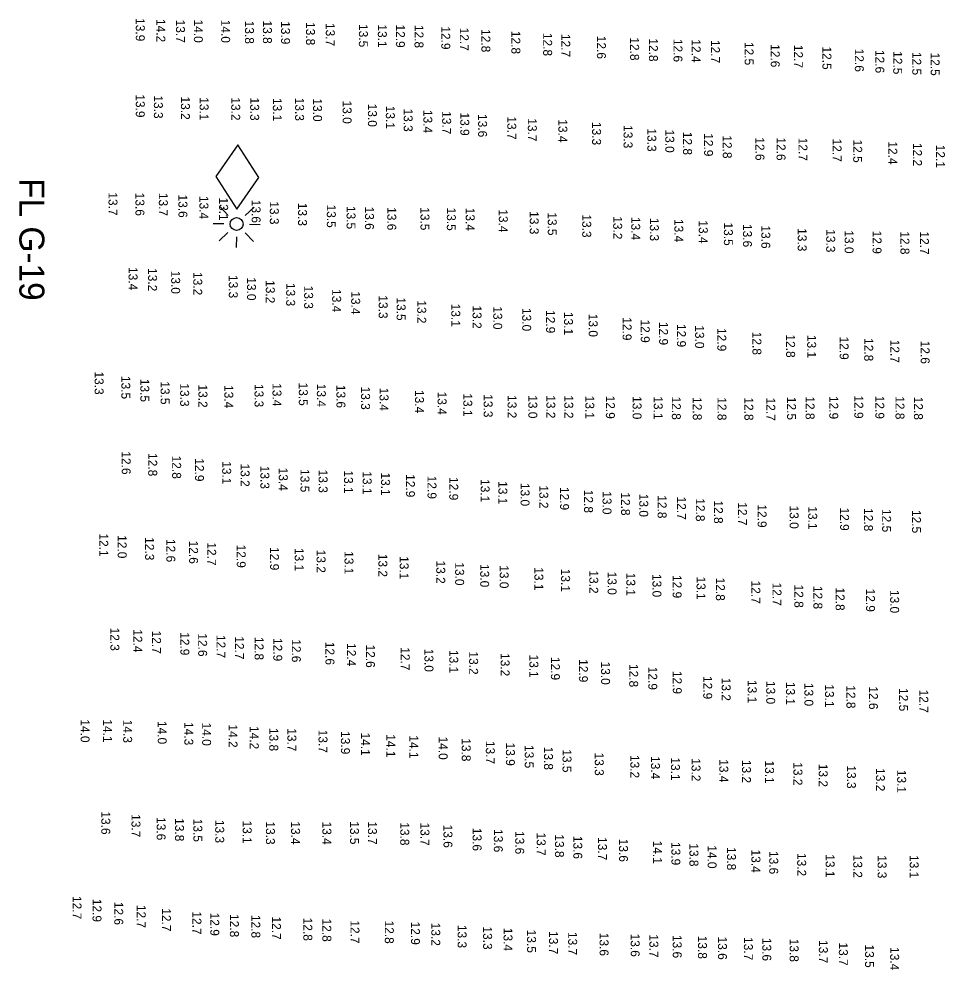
# Model space of a CAD drawing. Extents: x 988130 to 1132882, y 654656 to 841453.
# Drawn here: x 1109665 to 1110184, y 669094 to 669627 of the extents above; entities that cross this region are included whole.
import ezdxf

# ---------------------------------------------------------------- set-up
doc = ezdxf.new("R2010")
doc.units = 0
doc.layers.add('V-CHAN-NAID', color=7, linetype='Continuous')
doc.layers.add('V-TOPO-SOUN', color=7, linetype='Continuous')

msp = doc.modelspace()

# ---------------------------------------------------------------- linework, layer by layer
at = {"layer": 'V-CHAN-NAID'}
for p, q in [((1109781.78, 669517.3), (1109777.07, 669522.19)), ((1109791.38, 669517.14), (1109796.27, 669521.85)), ((1109779.3, 669512.55), (1109773.3, 669512.65)), ((1109793.7, 669512.29), (1109799.7, 669512.19)), ((1109776.73, 669502.99), (1109781.62, 669507.7)), ((1109795.93, 669502.65), (1109791.22, 669507.54)), ((1109786.37, 669505.22), (1109786.27, 669499.22))]:
    msp.add_line(p, q, dxfattribs=at)
msp.add_lwpolyline([(1109786.65, 669520.82), (1109798.96, 669538.61), (1109787.27, 669556.81), (1109774.96, 669539.03)], close=True, dxfattribs=at)
msp.add_circle((1109786.5, 669512.42), 3.6, dxfattribs=at)

# ---------------------------------------------------------------- texts
msp.add_text('FL G-19', height=14, rotation=270, dxfattribs=at).set_placement((1109664.76, 669538.17))
at = {"layer": 'V-TOPO-SOUN'}
for s, p in [('13.9 ', (1109730.03, 669627.83)), ('14.2 ', (1109741.59, 669627.32)), ('13.7 ', (1109752.54, 669626.98)), ('14.0 ', (1109762.56, 669627.03)), ('14.0 ', (1109777.87, 669626.93)), ('13.8 ', (1109791.22, 669626.38)), ('13.8 ', (1109801.28, 669626.49)), ('13.9 ', (1109811.45, 669626.12)), ('13.8 ', (1109825.44, 669625.61)), ('13.7 ', (1109836.52, 669625.1)), ('13.5 ', (1109855.06, 669624.5)), ('13.1 ', (1109865.69, 669624.29)), ('12.9 ', (1109875.82, 669624.25)), ('12.8 ', (1109886.24, 669624.05)), ('12.9 ', (1109901.24, 669623.23)), ('12.7 ', (1109911.63, 669622.48)), ('12.8 ', (1109923.73, 669621.67)), ('12.8 ', (1109940.54, 669620.7)), ('12.8 ', (1109958.34, 669619.57)), ('12.7 ', (1109968.51, 669618.99)), ('12.6 ', (1109988.47, 669617.94)), ('12.8 ', (1110007.09, 669617.06)), ('12.8 ', (1110017.62, 669616.49)), ('12.6 ', (1110031.38, 669616.19)), ('12.4 ', (1110041.58, 669615.93)), ('12.7 ', (1110052.36, 669615.59)), ('12.5 ', (1110071.25, 669614.45)), ('12.6 ', (1110085.91, 669613.24)), ('12.7 ', (1110098.86, 669612.87)), ('12.5 ', (1110114.87, 669611.94)), ('12.6 ', (1110133.01, 669610.71)), ('12.6 ', (1110144.53, 669609.99)), ('12.5 ', (1110154.53, 669609.31)), ('12.5 ', (1110165.2, 669608.88)), ('12.5 ', (1110175.53, 669608.53)), ('13.9 ', (1109730.03, 669585.14)), ('13.3 ', (1109740.16, 669584.53)), ('13.2 ', (1109755.32, 669583.91)), ('13.1 ', (1109765.79, 669583.52)), ('13.2 ', (1109783.51, 669583.44)), ('13.3 ', (1109794.14, 669583.36)), ('13.1 ', (1109806.84, 669583.06)), ('13.3 ', (1109819.32, 669583.23)), ('13.0 ', (1109829.38, 669582.84)), ('13.0 ', (1109845.96, 669581.63)), ('13.0 ', (1109860.12, 669579.88)), ('13.1 ', (1109870.17, 669578.73)), ('13.3 ', (1109880.18, 669577.17)), ('13.4 ', (1109891.2, 669576.41)), ('13.7 ', (1109901.74, 669575.69)), ('13.9 ', (1109911.9, 669574.94)), ('13.6 ', (1109921.88, 669574.09)), ('13.7 ', (1109938.23, 669572.77)), ('13.7 ', (1109949.74, 669571.72)), ('13.4 ', (1109966.88, 669571.13)), ('13.3 ', (1109985.78, 669569.66)), ('13.3 ', (1110003.4, 669567.88)), ('13.3 ', (1110016.74, 669566.02)), ('13.0 ', (1110026.78, 669565.4)), ('12.8 ', (1110036.74, 669564.12)), ('12.9 ', (1110048.51, 669563.34)), ('12.8 ', (1110059.02, 669562.16)), ('12.6 ', (1110077.32, 669561.04)), ('12.6 ', (1110089.16, 669561.01)), ('12.7 ', (1110101.44, 669560.82)), ('12.7 ', (1110120.55, 669560.32)), ('12.5 ', (1110132.1, 669559.8)), ('12.4 ', (1110151.78, 669558.76)), ('12.2 ', (1110165.6, 669557.89)), ('12.1 ', (1110178.46, 669556.89)), ('13.7 ', (1109714.73, 669530.2)), ('13.6 ', (1109729.83, 669530.01)), ('13.7 ', (1109742.93, 669529.91)), ('13.6 ', (1109753.93, 669529)), ('13.4 ', (1109765.7, 669528.21)), ('13.1 ', (1109776.73, 669527.34)), ('13.6 ', (1109794.94, 669526.06)), ('13.3 ', (1109805.14, 669525.2)), ('13.3 ', (1109820.97, 669524.35)), ('13.5 ', (1109837.1, 669523.37)), ('13.5 ', (1109848.14, 669522.59)), ('13.6 ', (1109858.49, 669522.24)), ('13.6 ', (1109870.97, 669521.9)), ('13.5 ', (1109889.58, 669521.89)), ('13.5 ', (1109904.36, 669521.68)), ('13.4 ', (1109914.94, 669521.58)), ('13.4 ', (1109933.48, 669520.72)), ('13.3 ', (1109950.81, 669519.66)), ('13.5 ', (1109960.93, 669519.03)), ('13.3 ', (1109980.24, 669517.85)), ('13.2 ', (1109997.59, 669516.84)), ('13.4 ', (1110007.7, 669516.45)), ('13.3 ', (1110018.15, 669515.91)), ('13.4 ', (1110031.87, 669515.28)), ('13.4 ', (1110045.57, 669514.51)), ('13.5 ', (1110059.63, 669513.31)), ('13.6 ', (1110070.32, 669512.48)), ('13.6 ', (1110080.6, 669511.69)), ('13.3 ', (1110101.01, 669510.14)), ('13.3 ', (1110116.97, 669509.55)), ('13.0 ', (1110127.3, 669508.92)), ('12.9 ', (1110142.95, 669508.73)), ('12.8 ', (1110158.59, 669508.38)), ('12.7 ', (1110169.56, 669508.3)), ('13.4 ', (1109725.98, 669488.35)), ('13.2 ', (1109736.93, 669487.75)), ('13.0 ', (1109749.85, 669486.3)), ('13.2 ', (1109762.23, 669485.54)), ('13.3 ', (1109782.15, 669483.9)), ('13.0 ', (1109792.37, 669482.62)), ('13.2 ', (1109802.89, 669481.01)), ('13.3 ', (1109814.31, 669479.43)), ('13.3 ', (1109824.39, 669477.92)), ('13.4 ', (1109840.09, 669475.99)), ('13.4 ', (1109850.75, 669474.75)), ('13.3 ', (1109866.16, 669472.49)), ('13.5 ', (1109876.21, 669471.32)), ('13.2 ', (1109887.76, 669469.73)), ('13.1 ', (1109906.84, 669467.83)), ('13.2 ', (1109918.77, 669466.8)), ('13.0 ', (1109930.35, 669466.36)), ('13.0 ', (1109946.59, 669465.41)), ('12.9 ', (1109959.98, 669464.23)), ('13.1 ', (1109970.03, 669463.22)), ('13.0 ', (1109983.86, 669462.17)), ('12.9 ', (1110002.87, 669460.22)), ('12.9 ', (1110013.05, 669458.93)), ('12.9 ', (1110023.3, 669457.6)), ('12.9 ', (1110033.32, 669456.47)), ('13.0 ', (1110043.52, 669455.74)), ('12.9 ', (1110055.95, 669454.18)), ('12.8 ', (1110075.64, 669452.1)), ('12.8 ', (1110094.51, 669450.58)), ('13.1 ', (1110106.31, 669450.34)), ('12.9 ', (1110124.49, 669449.42)), ('12.8 ', (1110138.29, 669448.54)), ('12.7 ', (1110152.98, 669447.64)), ('12.6 ', (1110169.93, 669447.08)), ('13.3 ', (1109706.96, 669429.84)), ('13.5 ', (1109721.93, 669427.35)), ('13.5 ', (1109732.56, 669425.73)), ('13.5 ', (1109743.93, 669424.33)), ('13.3 ', (1109754.9, 669423.18)), ('13.2 ', (1109765.15, 669422.56)), ('13.4 ', (1109779.65, 669422.22)), ('13.3 ', (1109796.58, 669422.83)), ('13.4 ', (1109806.64, 669423.28)), ('13.5 ', (1109821.39, 669423.63)), ('13.4 ', (1109831.51, 669422.94)), ('13.6 ', (1109842.49, 669422.35)), ('13.3 ', (1109856.3, 669421.39)), ('13.4 ', (1109866.64, 669420.73)), ('13.4 ', (1109886.5, 669419.46)), ('13.4 ', (1109899.17, 669418.55)), ('13.1 ', (1109913.57, 669417.58)), ('13.3 ', (1109924.98, 669417.08)), ('13.2 ', (1109938.39, 669416.59)), ('13.0 ', (1109950.04, 669416.53)), ('13.2 ', (1109960.13, 669416.54)), ('13.2 ', (1109970.19, 669416.49)), ('13.1 ', (1109981.96, 669416.27)), ('12.9 ', (1109993.49, 669416.31)), ('13.0 ', (1110008.45, 669416.02)), ('13.1 ', (1110020.31, 669415.94)), ('12.8 ', (1110030.46, 669415.76)), ('12.5 ', (1110095.05, 669415.63)), ('12.8 ', (1110105.42, 669415.89)), ('12.9 ', (1110118.68, 669416.12)), ('12.9 ', (1110132.71, 669416.43)), ('12.9 ', (1110144.51, 669416.25)), ('12.8 ', (1110155.8, 669415.96)), ('12.8 ', (1110166.13, 669415.69)), ('12.8 ', (1110042.21, 669415.47)), ('12.8 ', (1110056.04, 669415.41)), ('12.8 ', (1110071.12, 669415.32)), ('12.7 ', (1110083.39, 669415.22)), ('12.6 ', (1109722.14, 669385.09)), ('12.8 ', (1109737, 669384.11)), ('12.8 ', (1109750.41, 669382.68)), ('12.9 ', (1109763.2, 669381.21)), ('13.1 ', (1109778.45, 669379.57)), ('13.2 ', (1109788.77, 669378.25)), ('13.3 ', (1109799.88, 669377.02)), ('13.4 ', (1109810.17, 669375.95)), ('13.5 ', (1109822.33, 669375.13)), ('13.3 ', (1109832.48, 669374.85)), ('13.1 ', (1109846.74, 669374.42)), ('13.1 ', (1109857.21, 669373.89)), ('13.1 ', (1109867.52, 669373.25)), ('12.9 ', (1109881.42, 669372.32)), ('12.9 ', (1109893.52, 669371.43)), ('12.9 ', (1109905.69, 669370.68)), ('13.1 ', (1109923.29, 669369.53)), ('13.1 ', (1109933.24, 669368.37)), ('13.0 ', (1109945.68, 669367.39)), ('13.2 ', (1109956.16, 669366.06)), ('12.9 ', (1109967.8, 669365.13)), ('12.8 ', (1109981.27, 669363.55)), ('13.0 ', (1109991.61, 669362.73)), ('12.8 ', (1110002.02, 669362.11)), ('13.0 ', (1110012.2, 669361.31)), ('12.8 ', (1110022.49, 669360.49)), ('12.7 ', (1110033.38, 669359.74)), ('12.8 ', (1110043.9, 669358.78)), ('12.8 ', (1110054.05, 669357.57)), ('12.7 ', (1110067.58, 669356.54)), ('12.9 ', (1110078.56, 669355.36)), ('13.0 ', (1110096.49, 669354.7)), ('13.1 ', (1110106.89, 669354.27)), ('12.9 ', (1110124.76, 669353.61)), ('12.8 ', (1110138.15, 669353.28)), ('12.5 ', (1110148.33, 669352.76)), ('12.5 ', (1110165.05, 669352.23)), ('12.1 ', (1109709.57, 669339.08)), ('12.0 ', (1109719.89, 669338.12)), ('12.3 ', (1109735.26, 669337)), ('12.6 ', (1109747.16, 669335.98)), ('12.6 ', (1109759.9, 669335.06)), ('12.7 ', (1109770.05, 669334.08)), ('12.9 ', (1109786.61, 669332.81)), ('12.9 ', (1109805.29, 669331.42)), ('13.1 ', (1109819.1, 669330.96)), ('13.2 ', (1109831.35, 669329.98)), ('13.1 ', (1109847, 669329.15)), ('13.2 ', (1109866, 669327.68)), ('13.1 ', (1109877.94, 669326.35)), ('13.2 ', (1109898.42, 669323.91)), ('13.0 ', (1109909.02, 669322.91)), ('13.0 ', (1109923.05, 669321.92)), ('13.0 ', (1109933.97, 669321.28)), ('13.1 ', (1109953.43, 669320.15)), ('13.1 ', (1109968.41, 669319.31)), ('13.2 ', (1109984.18, 669318.38)), ('13.0 ', (1109994.45, 669317.69)), ('13.1 ', (1110004.98, 669317.06)), ('13.0 ', (1110019.59, 669316.37)), ('12.9 ', (1110030.91, 669315.8)), ('13.1 ', (1110044.3, 669314.94)), ('12.8 ', (1110055.14, 669314.33)), ('12.7 ', (1110075.04, 669312.68)), ('12.7 ', (1110086.88, 669311.52)), ('12.8 ', (1110099.15, 669310.44)), ('12.8 ', (1110109.81, 669309.69)), ('12.8 ', (1110122.25, 669308.81)), ('12.9 ', (1110139.3, 669308.14)), ('13.0 ', (1110152.82, 669307.41)), ('12.3 ', (1109715.79, 669286.3)), ('12.4 ', (1109728.59, 669285.4)), ('12.7 ', (1109739.15, 669284.64)), ('12.9 ', (1109755, 669283.76)), ('12.6 ', (1109764.98, 669283.11)), ('12.7 ', (1109775.26, 669282.22)), ('12.7 ', (1109785.64, 669281.45)), ('12.8 ', (1109796.62, 669281.12)), ('12.9 ', (1109807.06, 669280.49)), ('12.6 ', (1109817.48, 669279.83)), ('12.6 ', (1109836.33, 669278.37)), ('12.4 ', (1109848.38, 669277.64)), ('12.6 ', (1109859.03, 669276.85)), ('12.7 ', (1109878.55, 669275.31)), ('13.0 ', (1109891.82, 669274.5)), ('13.1 ', (1109905.72, 669273.78)), ('13.2 ', (1109916.86, 669272.97)), ('13.2 ', (1109934.51, 669272.04)), ('13.1 ', (1109950.64, 669271.24)), ('12.9 ', (1109962.67, 669269.9)), ('12.9 ', (1109978.37, 669268.66)), ('13.0 ', (1109990.8, 669267.3)), ('12.8 ', (1110006.55, 669265.95)), ('12.9 ', (1110017.26, 669264.42)), ('12.9 ', (1110031, 669262.09)), ('12.9 ', (1110048.04, 669259.2)), ('13.2 ', (1110058.4, 669258.24)), ('13.1 ', (1110073.02, 669256.96)), ('13.0 ', (1110083.34, 669256.45)), ('13.1 ', (1110094.46, 669255.92)), ('13.0 ', (1110104.75, 669255.34)), ('13.1 ', (1110116.29, 669254.57)), ('12.8 ', (1110128.31, 669253.99)), ('12.6 ', (1110140.91, 669253.43)), ('12.5 ', (1110157.84, 669252.45)), ('12.7 ', (1110169.19, 669251.57)), ('14.0 ', (1109699.12, 669234.92)), ('14.1 ', (1109711.72, 669234.94)), ('14.3 ', (1109722.95, 669234.71)), ('14.0 ', (1109742.31, 669234)), ('14.3 ', (1109757.22, 669233.41)), ('14.0 ', (1109767.22, 669233.1)), ('14.2 ', (1109782.01, 669232.06)), ('14.2 ', (1109793.92, 669231.17)), ('13.8 ', (1109804.84, 669230.11)), ('13.7 ', (1109815, 669229.95)), ('13.7 ', (1109832.43, 669229.12)), ('13.9 ', (1109844.99, 669228.33)), ('14.1 ', (1109856.21, 669227.53)), ('14.1 ', (1109870.46, 669226.59)), ('14.1 ', (1109883.38, 669225.97)), ('14.0 ', (1109899.8, 669225.3)), ('13.8 ', (1109912.71, 669224.34)), ('13.7 ', (1109926.21, 669222.85)), ('13.9 ', (1109937.46, 669221.89)), ('13.5 ', (1109948.03, 669220.54)), ('13.8 ', (1109958.82, 669219.56)), ('13.5 ', (1109969.19, 669218.15)), ('13.3 ', (1109987.28, 669216.32)), ('13.2 ', (1110007.21, 669214.97)), ('13.4 ', (1110018.76, 669214.33)), ('13.1 ', (1110029.97, 669213.61)), ('13.2 ', (1110041.5, 669213.15)), ('13.4 ', (1110057.06, 669212.58)), ('13.2 ', (1110069.78, 669212.21)), ('13.1 ', (1110082.73, 669211.87)), ('13.2 ', (1110098.62, 669210.88)), ('13.2 ', (1110112.8, 669210.01)), ('13.3 ', (1110128.58, 669209.12)), ('13.2 ', (1110144.83, 669207.59)), ('13.1 ', (1110156.75, 669206.63)), ('13.6 ', (1109710.69, 669183.36)), ('13.7 ', (1109727.61, 669181.81)), ('13.6 ', (1109741.72, 669180.15)), ('13.8 ', (1109752.03, 669179.56)), ('13.5 ', (1109762.3, 669179.24)), ('13.3 ', (1109774.54, 669178.6)), ('13.1 ', (1109789.97, 669178.23)), ('13.3 ', (1109802.96, 669177.73)), ('13.4 ', (1109817.07, 669177.78)), ('13.4 ', (1109834.62, 669177.66)), ('13.5 ', (1109850.1, 669177.82)), ('13.7 ', (1109860.13, 669177.75)), ('13.8 ', (1109878.25, 669177.24)), ('13.7 ', (1109889.57, 669177.11)), ('13.6 ', (1109902.46, 669175.93)), ('13.6 ', (1109918.79, 669174.14)), ('13.6 ', (1109930.7, 669173.42)), ('13.6 ', (1109942.69, 669172.33)), ('13.7 ', (1109954.74, 669171.51)), ('13.8 ', (1109964.98, 669170.48)), ('13.6 ', (1109975.25, 669169.66)), ('13.7 ', (1109989.08, 669168.93)), ('13.6 ', (1110000.86, 669168.03)), ('14.1 ', (1110019.95, 669166.94)), ('13.9 ', (1110030.22, 669166.18)), ('13.8 ', (1110040.33, 669165.46)), ('14.0 ', (1110050.53, 669164.36)), ('13.8 ', (1110061.36, 669163.36)), ('13.4 ', (1110075.08, 669161.99)), ('13.6 ', (1110085.05, 669161.14)), ('13.2 ', (1110100.71, 669160.01)), ('13.1 ', (1110116.66, 669159.33)), ('13.2 ', (1110132.12, 669159.08)), ('13.3 ', (1110145.78, 669158.81)), ('13.1 ', (1110163.75, 669158.89)), ('12.7 ', (1109694.57, 669135.94)), ('12.9 ', (1109705.78, 669134.37)), ('12.6 ', (1109717.94, 669132.67)), ('12.7 ', (1109730.59, 669130.98)), ('12.7 ', (1109744.66, 669129.08)), ('12.7 ', (1109761.78, 669127.32)), ('12.9 ', (1109771.77, 669126.61)), ('12.8 ', (1109782.76, 669125.82)), ('12.8 ', (1109794.78, 669125.36)), ('12.7 ', (1109806.38, 669124.45)), ('12.8 ', (1109823.93, 669123.79)), ('12.8 ', (1109834.6, 669123.3)), ('12.7 ', (1109850.36, 669122.28)), ('12.8 ', (1109869.6, 669122.18)), ('12.9 ', (1109884.26, 669121.58)), ('13.2 ', (1109895.63, 669120.98)), ('13.3 ', (1109910.39, 669119.76)), ('13.3 ', (1109924.69, 669118.9)), ('13.4 ', (1109936.13, 669118.11)), ('13.5 ', (1109949.32, 669117.06)), ('13.7 ', (1109961.63, 669116.26)), ('13.7 ', (1109972.35, 669115.79)), ('13.6 ', (1109989.96, 669115.33)), ('13.6 ', (1110007.42, 669114.85)), ('13.7 ', (1110017.89, 669114.45)), ('13.6 ', (1110030.96, 669114.11)), ('13.8 ', (1110045.11, 669113.69)), ('13.6 ', (1110056.32, 669113.21)), ('13.7 ', (1110070.84, 669112.92)), ('13.6 ', (1110081.18, 669112.48)), ('13.8 ', (1110096.5, 669112)), ('13.7 ', (1110112.85, 669111.23)), ('13.7 ', (1110124.07, 669109.88)), ('13.5 ', (1110138.75, 669108.76)), ('13.4 ', (1110152.83, 669107.3))]:
    msp.add_text(s, height=5, rotation=270, dxfattribs=at).set_placement(p)

doc.saveas('drawing.dxf')
